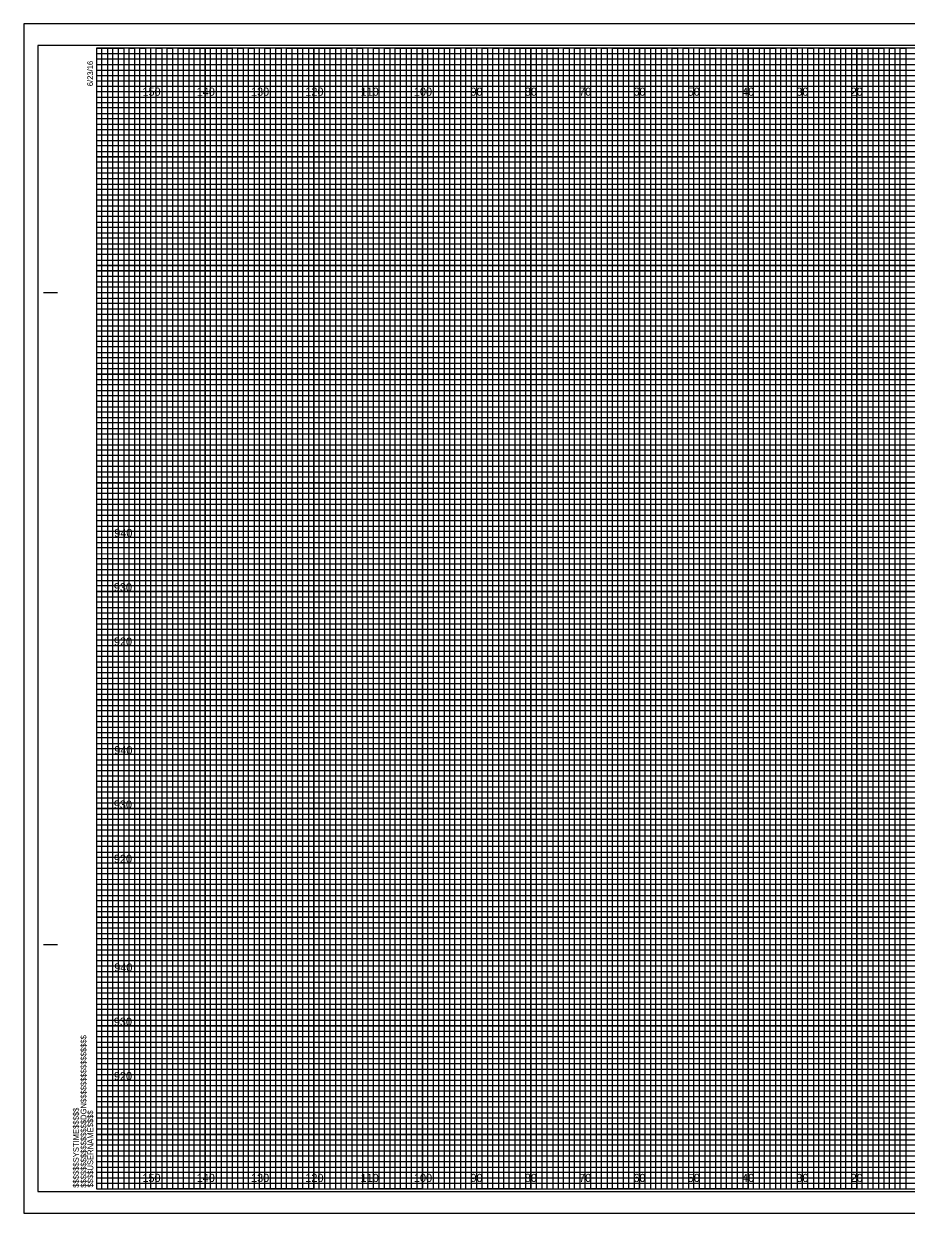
# Model space of a CAD drawing. Extents: x -13 to 323, y -4 to 214.
# Drawn here: x -13.4 to 149.1, y -4.5 to 214.5 of the extents above; entities that cross this region are included whole.
import ezdxf

# ---------------------------------------------------------------- set-up
doc = ezdxf.new("R2010")
doc.units = 0
for name, color, linetype in [('Prop XS Elevation Labels', 7, 'Continuous'), ('Prop XS Offset Labels', 7, 'Continuous'), ('Sheet Cross Section CELL', 7, 'Continuous'), ('Sheet Cross Section Grid Major CELL', 7, 'Continuous'), ('Sheet Cross Section Grid Middle CELL', 7, 'Continuous'), ('Sheet Cross Section Grid Minor 1 CELL', 7, 'Continuous'), ('Sheet Cross Section Grid Minor 2 CELL', 7, 'Continuous'), ('Sheet Cutting Line CELL', 7, 'Continuous'), ('Sheet DOT Grid CELL', 7, 'Continuous'), ('Sheet Plot Border Inside CELL', 7, 'Continuous'), ('Sheet Plot Border Outside CELL', 7, 'Continuous')]:
    doc.layers.add(name, color=color, linetype=linetype)

msp = doc.modelspace()

# ---------------------------------------------------------------- linework, layer by layer
at = {"layer": 'Sheet Cross Section CELL'}
for p, q in [((-9.8, 165), (-7.3, 165)), ((-9.7, 165), (-7.2, 165)), ((-9.8, 45), (-7.3, 45)), ((-9.7, 45), (-7.2, 45)), ((0, 0), (0, 0)), ((0, 0), (0, 0)), ((0, 0), (0, 0)), ((0, 0), (0, 0)), ((0, 0), (0, 0)), ((0, 0), (0, 0)), ((0, 0), (0, 0))]:
    msp.add_line(p, q, dxfattribs=at)
msp.add_lwpolyline([(320, 210), (0, 210), (0, 0), (320, 0)], close=True, dxfattribs=at)
at = {"layer": 'Sheet Cross Section Grid Major CELL'}
for p, q in [((10, 210), (0, 210)), ((10, 0), (10, 210)), ((30, 210), (20, 210)), ((20, 210), (20, 0)), ((30, 0), (30, 210)), ((50, 210), (40, 210)), ((40, 210), (40, 0)), ((50, 0), (50, 210)), ((70, 210), (60, 210)), ((60, 210), (60, 0)), ((70, 0), (70, 210)), ((90, 210), (80, 210)), ((80, 210), (80, 0)), ((90, 0), (90, 210)), ((110, 210), (100, 210)), ((100, 210), (100, 0)), ((110, 0), (110, 210)), ((130, 210), (120, 210)), ((120, 210), (120, 0)), ((130, 0), (130, 210)), ((150, 210), (140, 210)), ((140, 210), (140, 0)), ((20, 0), (10, 0)), ((40, 0), (30, 0)), ((60, 0), (50, 0)), ((80, 0), (70, 0)), ((100, 0), (90, 0)), ((120, 0), (110, 0)), ((140, 0), (130, 0))]:
    msp.add_line(p, q, dxfattribs=at)
for points in [[(0, 200), (320, 200), (320, 190), (0, 190)], [(0, 180), (320, 180), (320, 170), (0, 170)], [(0, 160), (320, 160), (320, 150), (0, 150)], [(0, 140), (320, 140), (320, 130), (0, 130)], [(0, 120), (320, 120), (320, 110), (0, 110)], [(0, 100), (320, 100), (320, 90), (0, 90)], [(0, 80), (320, 80), (320, 70), (0, 70)], [(0, 60), (320, 60), (320, 50), (0, 50)], [(0, 40), (320, 40), (320, 30), (0, 30)], [(0, 20), (320, 20), (320, 10), (0, 10)]]:
    msp.add_lwpolyline(points, dxfattribs=at)
at = {"layer": 'Sheet Cross Section Grid Middle CELL'}
for points in [[(0, 210), (5, 210), (5, 0), (15, 0), (15, 210), (25, 210), (25, 0), (35, 0), (35, 210), (45, 210), (45, 0), (55, 0), (55, 210), (65, 210), (65, 0), (75, 0), (75, 210), (85, 210), (85, 0), (95, 0), (95, 210), (105, 210), (105, 0), (115, 0), (115, 210), (125, 210), (125, 0), (135, 0), (135, 210), (145, 210), (145, 0), (155, 0)], [(0, 205), (275, 205)], [(0, 185), (320, 185), (320, 195), (0, 195)], [(0, 165), (320, 165), (320, 175), (0, 175)], [(0, 145), (320, 145), (320, 155), (0, 155)], [(0, 125), (320, 125), (320, 135), (0, 135)], [(0, 105), (320, 105), (320, 115), (0, 115)], [(0, 85), (320, 85), (320, 95), (0, 95)], [(0, 65), (320, 65), (320, 75), (0, 75)], [(0, 45), (320, 45), (320, 55), (0, 55)], [(0, 25), (320, 25), (320, 35), (0, 35)], [(0, 5), (320, 5), (320, 15), (0, 15)]]:
    msp.add_lwpolyline(points, dxfattribs=at)
at = {"layer": 'Sheet Cross Section Grid Minor 1 CELL'}
for p, q in [((0, 209), (260, 209)), ((260, 207.98), (0, 207.98)), ((0, 207.98), (0, 207)), ((0, 207), (260, 207)), ((260, 205.89), (0, 205.89)), ((0, 205.89), (0, 204)), ((0, 204), (320, 204))]:
    msp.add_line(p, q, dxfattribs=at)
for points in [[(0, 203), (270, 203), (320, 203), (320, 202), (0, 202)], [(0, 201), (320, 201), (320, 199), (0, 199)], [(0, 198), (320, 198), (320, 197), (0, 196.98)], [(0, 196), (320, 196), (320, 194), (0, 194)], [(0, 193), (320, 193), (320, 192), (0, 192)], [(0, 191), (320, 191), (320, 189), (0, 189)], [(0, 188), (320, 188), (320, 187), (0, 187)], [(0, 186), (320, 186), (320, 184), (0, 184)], [(0, 183), (320, 183), (320, 182), (0, 182)], [(0, 181), (320, 181), (320, 179), (0, 179)], [(0, 178), (320, 178), (320, 177), (0, 177)], [(0, 176), (320, 176), (320, 173.95), (320, 173), (320, 172), (0, 172)], [(0, 174), (320, 174), (320, 173), (0, 173)], [(0, 171), (320, 171), (320, 169), (0, 169.03)], [(0, 169.03), (320, 169), (320, 168), (0, 168)], [(0, 167), (320, 167), (320, 166), (0, 166)], [(0, 164), (320, 164), (320, 163), (0, 163)], [(0, 162), (320, 162), (320, 161), (0, 161)], [(-0.07, 158.89), (320, 158.89), (320, 157.88), (-0.07, 157.88)], [(0, 157), (320, 157), (320, 156), (0, 156)], [(0, 154), (320, 154), (320, 153), (0, 153)], [(0, 152), (320, 152), (320, 151), (0, 151)], [(0, 149), (320, 149), (320, 148), (0, 148)], [(0, 147), (320, 147), (320, 146), (0, 146)], [(0, 144), (320, 144), (320, 143), (0, 143)], [(0, 142), (320, 142), (320, 141), (0, 141)], [(0, 139), (320, 139), (319.99, 137.98), (0, 138)], [(0, 137), (320, 137), (320, 136), (0, 136)], [(0, 134), (320, 134), (320, 133), (0, 133)], [(0, 132), (320, 132), (320, 131), (0, 131)], [(0, 129), (320, 129), (320, 128), (0, 128)], [(0, 127), (320, 127), (320, 126), (0, 126)], [(0, 124), (320, 124), (320, 123), (0, 123)], [(0, 122), (320, 122), (320, 121), (0, 121)], [(0, 119), (320, 119), (320, 118), (0, 118)], [(0, 116.99), (320.07, 116.91), (320, 116), (0, 116)], [(0, 114), (320, 114), (320, 113), (0, 113)], [(0, 112), (320, 112), (320, 111), (0, 111)], [(0, 109), (320, 109), (320, 108), (0, 108)], [(0, 107), (320, 107), (320, 106), (0, 106)], [(0, 104), (320, 104), (320, 103), (0, 103)], [(0, 102), (320, 102), (320, 101), (0, 101)], [(0, 99), (320, 99), (320, 98), (0, 98)], [(0, 97), (320, 97), (320, 96), (0, 96)], [(0, 94), (320, 94), (320, 93), (0, 93)], [(0, 92), (320, 92), (320, 91), (0, 91)], [(0, 89), (320, 89), (320, 88), (0, 88)], [(0, 87), (320, 87), (320, 86), (0, 86)], [(0, 84), (320, 84), (320, 83), (0, 83)], [(0, 82), (320, 82), (320, 81), (0, 81)], [(0, 79), (320, 79), (319.99, 77.98), (0, 78)], [(0, 77), (320, 77), (320, 76), (0, 76)], [(0, 74), (320, 74), (320, 73), (0, 73)], [(0, 72), (320, 72), (320, 71), (0, 71)], [(0, 69), (320, 69), (320, 68), (0, 68)], [(0, 67), (320, 67), (320, 66), (0, 66)], [(0, 64), (320, 64), (320, 63), (0, 63)], [(0, 62), (320, 62), (320, 61), (0, 61)], [(0, 59), (320, 59), (320, 58), (0, 58)], [(0, 56.99), (320.07, 56.91), (320, 56), (0, 56)], [(0, 54), (320, 54), (320, 53), (0, 53)], [(0, 52), (320, 52), (320, 51), (0, 51)], [(0, 49), (320, 49), (320, 48), (0, 48)], [(0, 47), (320, 47), (320, 46), (0, 46)], [(0, 44), (320, 44), (320, 43), (0, 43)], [(0, 42), (320, 42), (320, 41), (0, 41)], [(0, 39), (320, 39), (320, 38), (0, 38)], [(0, 37), (320, 37), (320, 36), (0, 36)], [(0, 34), (320, 34), (320, 33), (0, 33)], [(0, 32), (320, 32), (320, 31), (0, 31)], [(0, 29), (320, 29), (320, 28), (0, 28)], [(0, 27), (320, 27), (320, 26), (0, 26)], [(0, 24), (320, 24), (320, 23), (0, 23)], [(0, 22), (320, 22), (320, 21), (0, 21)], [(0, 19), (320, 19), (320, 18), (0, 18)], [(0, 17), (320, 17), (320, 16), (0, 16)], [(0, 14), (320, 14), (320, 13), (0, 13)], [(0, 12), (320, 12), (320, 11), (0, 11)], [(0, 9), (320, 9), (320, 8), (0, 8)], [(0, 7), (320, 7), (320, 6), (0, 6)], [(0, 4), (320, 4), (320, 3), (0, 3)], [(0, 2), (320, 2), (320, 1), (0, 1)]]:
    msp.add_lwpolyline(points, dxfattribs=at)
at = {"layer": 'Sheet Cross Section Grid Minor 2 CELL'}
for points in [[(0, 0), (1, 0), (1, 210), (2, 210), (2, 0)], [(2, 0), (3, 0), (3, 210), (4, 210), (4, 0)], [(5, 0), (6, 0), (6, 210), (7, 210), (7, 0)], [(7, 0), (8, 0), (8, 210), (9, 210), (9, 0)], [(10, 0), (11, 0), (11, 210), (12, 210), (12, 0)], [(12, 0), (13, 0), (13, 210), (14, 210), (14, 0)], [(15, 0), (16, 0), (16, 210), (17, 210), (17, 0)], [(17, 0), (18, 0), (18, 210), (19, 210), (19, 0)], [(20, 0), (21, 0), (21, 210), (22, 210), (22, 0)], [(22, 0), (23, 0), (23, 210), (24, 210), (24, 0)], [(25, 0), (26, 0), (26, 210), (27, 210), (27, 0)], [(27, 0), (28, 0), (28, 210), (29, 210), (29, 0)], [(30, 0), (31, 0), (31, 210), (32, 210), (32, 0)], [(32, 0), (33, 0), (33, 210), (34, 210), (34, 0)], [(35, 0), (36, 0), (36, 210), (37, 210), (37, 0)], [(37, 0), (38, 0), (38, 210), (39, 210), (39, 0)], [(40, 0), (41, 0), (41, 210), (42, 210), (42, 0)], [(42, 0), (43, 0), (43, 210), (44, 210), (44, 0)], [(45, 0), (46, 0), (46, 210), (47, 210), (47, 0)], [(47, 0), (48, 0), (48, 210), (49, 210), (49, 0)], [(50, 0), (51, 0), (51, 210), (52, 210), (52, 0)], [(52, 0), (53, 0), (53, 210), (54, 210), (54, 0)], [(55, 0), (56, 0), (56, 210), (57, 210), (57, 0)], [(57, 0), (58, 0), (58, 210), (59, 210), (59, 0)], [(60, 0), (61, 0), (61, 210), (62, 210), (62, 0)], [(62, 0), (63, 0), (63, 210), (64, 210), (64, 0)], [(65, 0), (66, 0), (66, 210), (67, 210), (67, 0)], [(67, 0), (68, 0), (68, 210), (69, 210), (69, 0)], [(70, 0), (71, 0), (71, 210), (72, 210), (72, 0)], [(72, 0), (73, 0), (73, 210), (74, 210), (74, 0)], [(75, 0), (76, 0), (76, 210), (77, 210), (77, 0)], [(77, 0), (78, 0), (78, 210), (79, 210), (79, 0)], [(80, 0), (81, 0), (81, 210), (82, 210), (82, 0)], [(82, 0), (83, 0), (83, 210), (84, 210), (84, 0)], [(85, 0), (86, 0), (86, 210), (87, 210), (87, 0)], [(87, 0), (88, 0), (88, 210), (89, 210), (89, 0)], [(90, 0), (91, 0), (91, 210), (92, 210), (92, 0)], [(92, 0), (93, 0), (93, 210), (94, 210), (94, 0)], [(95, 0), (96, 0), (96, 210), (97, 210), (97, 0)], [(97, 0), (98, 0), (98, 210), (99, 210), (99, 0)], [(100, 0), (101, 0), (101, 210), (102, 210), (102, 0)], [(102, 0), (103, 0), (103, 210), (104, 210), (104, 0)], [(105, 0), (106, 0), (106, 210), (107, 210), (107, 0)], [(107, 0), (108, 0), (108, 210), (109, 210), (109, 0)], [(110, 0), (111, 0), (111, 210), (112, 210), (112, 0)], [(112, 0), (113, 0), (113, 210), (114, 210), (114, 0)], [(115, 0), (116, 0), (116, 210), (117, 210), (117, 0)], [(117, 0), (118, 0), (118, 210), (119, 210), (119, 0)], [(120, 0), (121, 0), (121, 210), (122, 210), (122, 0)], [(122, 0), (123, 0), (123, 210), (124, 210), (124, 0)], [(125, 0), (126, 0), (126, 210), (127, 210), (127, 0)], [(127, 0), (128, 0), (128, 210), (129, 210), (129, 0)], [(130, 0), (131, 0), (131, 210), (132, 210), (132, 0)], [(132, 0), (133, 0), (133, 210), (134, 210), (134, 0)], [(135, 0), (136, 0), (136, 210), (137, 210), (137, 0)], [(137, 0), (138, 0), (138, 210), (139, 210), (139, 0)], [(140, 0), (141, 0), (141, 210), (142, 210), (142, 0)], [(142, 0), (143, 0), (143, 210), (144, 210), (144, 0)], [(145, 0), (146, 0), (146, 210), (147, 210), (147, 0)], [(147, 0), (148, 0), (148, 210), (149, 210), (149, 0)]]:
    msp.add_lwpolyline(points, dxfattribs=at)
at = {"layer": 'Sheet Cutting Line CELL'}
for p, q in [((323.3, 214.5), (-13.4, 214.5)), ((-13.4, 214.5), (-13.4, -4.5)), ((-13.4, -4.5), (323.3, -4.5))]:
    msp.add_line(p, q, dxfattribs=at)
at = {"layer": 'Sheet DOT Grid CELL'}
for p, q in [((10, 0), (10, 210)), ((20, 0), (20, 210)), ((30, 0), (30, 210)), ((40, 0), (40, 210)), ((50, 0), (50, 210)), ((60, 0), (60, 210)), ((70, 0), (70, 210)), ((80, 0), (80, 210)), ((90, 0), (90, 210)), ((100, 0), (100, 210)), ((110, 0), (110, 210)), ((120, 0), (120, 210)), ((130, 0), (130, 210)), ((140, 0), (140, 210)), ((0, 200), (320, 200)), ((0, 190), (320, 190)), ((0, 180), (320, 180)), ((0, 170), (320, 170)), ((0, 160), (320, 160)), ((0, 150), (320, 150)), ((0, 140), (320, 140)), ((0, 130), (320, 130)), ((0, 120), (320, 120)), ((0, 110), (320, 110)), ((0, 100), (320, 100)), ((0, 90), (320, 90)), ((0, 80), (320, 80)), ((0, 70), (320, 70)), ((0, 60), (320, 60)), ((0, 50), (320, 50)), ((0, 40), (320, 40)), ((0, 30), (320, 30)), ((0, 20), (320, 20)), ((0, 10), (320, 10))]:
    msp.add_line(p, q, dxfattribs=at)
at = {"layer": 'Sheet Plot Border Inside CELL'}
msp.add_lwpolyline([(-10.8, -0.5), (322.4, -0.5), (322.4, 210.5), (-10.8, 210.5)], close=True, dxfattribs=at)
at = {"layer": 'Sheet Plot Border Outside CELL'}
msp.add_lwpolyline([(-13.4, -4.5), (323.3, -4.5), (323.3, 214.5), (-13.4, 214.5)], close=True, dxfattribs=at)

# ---------------------------------------------------------------- texts
at = {"layer": 'Prop XS Elevation Labels'}
for s, p in [('940', (3.26, 120)), ('930', (3.18, 110)), ('920', (3.19, 100)), ('940', (3.26, 80)), ('930', (3.18, 70)), ('920', (3.19, 60)), ('940', (3.26, 40)), ('930', (3.18, 30)), ('920', (3.19, 20))]:
    msp.add_text(s, height=1.5, dxfattribs=at).set_placement(p)
at = {"layer": 'Prop XS Offset Labels'}
for s, p in [('150', (8.44, 201.25)), ('140', (18.44, 201.25)), ('130', (28.44, 201.25)), ('120', (38.44, 201.25)), ('110', (48.62, 201.25)), ('100', (58.44, 201.25)), ('90', (68.86, 201.25)), ('80', (78.86, 201.25)), ('70', (88.86, 201.25)), ('60', (98.86, 201.25)), ('50', (108.86, 201.25)), ('40', (118.86, 201.25)), ('30', (128.86, 201.25)), ('20', (138.86, 201.25)), ('150', (8.44, 1.25)), ('140', (18.44, 1.25)), ('130', (28.44, 1.25)), ('120', (38.44, 1.25)), ('110', (48.62, 1.25)), ('100', (58.44, 1.25)), ('90', (68.86, 1.25)), ('80', (78.86, 1.25)), ('70', (88.86, 1.25)), ('60', (98.86, 1.25)), ('50', (108.86, 1.25)), ('40', (118.86, 1.25)), ('30', (128.86, 1.25)), ('20', (138.86, 1.25))]:
    msp.add_text(s, height=1.5, dxfattribs=at).set_placement(p)
at = {"layer": 'Sheet Cross Section CELL'}
for s, p in [('6/23/16', (-0.65, 203)), ('$$$$$$$$$$$$$$$$DGN$$$$$$$$$$$$$$$$', (-1.88, 0.18)), ('$$$$$$SYSTIME$$$$$', (-3.26, 0.18)), ('$$$$USERNAME$$$$', (-0.62, 0.23))]:
    msp.add_text(s, height=1.05, rotation=90, dxfattribs=at).set_placement(p)

doc.saveas('drawing.dxf')
